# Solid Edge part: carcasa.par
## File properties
Author: USER
Template: Iso Metric Part.par
Last saved by: USER
Revision: 7
Application: Solid Edge
Accuracy: 0.990
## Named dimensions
RefPlane_5: FractionOfCurve = 0
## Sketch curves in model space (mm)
circle centre (117.8734, 0, 0.4116) radius 4.287
arc centre (0, 131.2933, 0) radius 15 from (0, 131.2933, 15) through (-0.4071, 146.2812, -0.4445) to (0, 131.2933, -15)
line (0, 131.2933, 0) -> (0, 131.2933, 15)
line (0, 131.2933, 0) -> (0, 131.2933, -15)
arc centre (0, 113.6061, 0) radius 7.5 from (0, 113.6061, -7.5) through (-1.8141, 120.88, 0.2222) to (0, 113.6061, 7.5)
line (0, 113.6061, 0) -> (0, 113.6061, 7.5)
line (0, 113.6061, 0) -> (0, 113.6061, -7.5)
circle centre (0, 0, 0) radius 113.6061
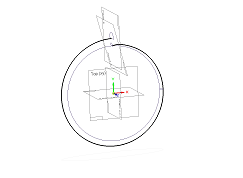
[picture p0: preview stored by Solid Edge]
